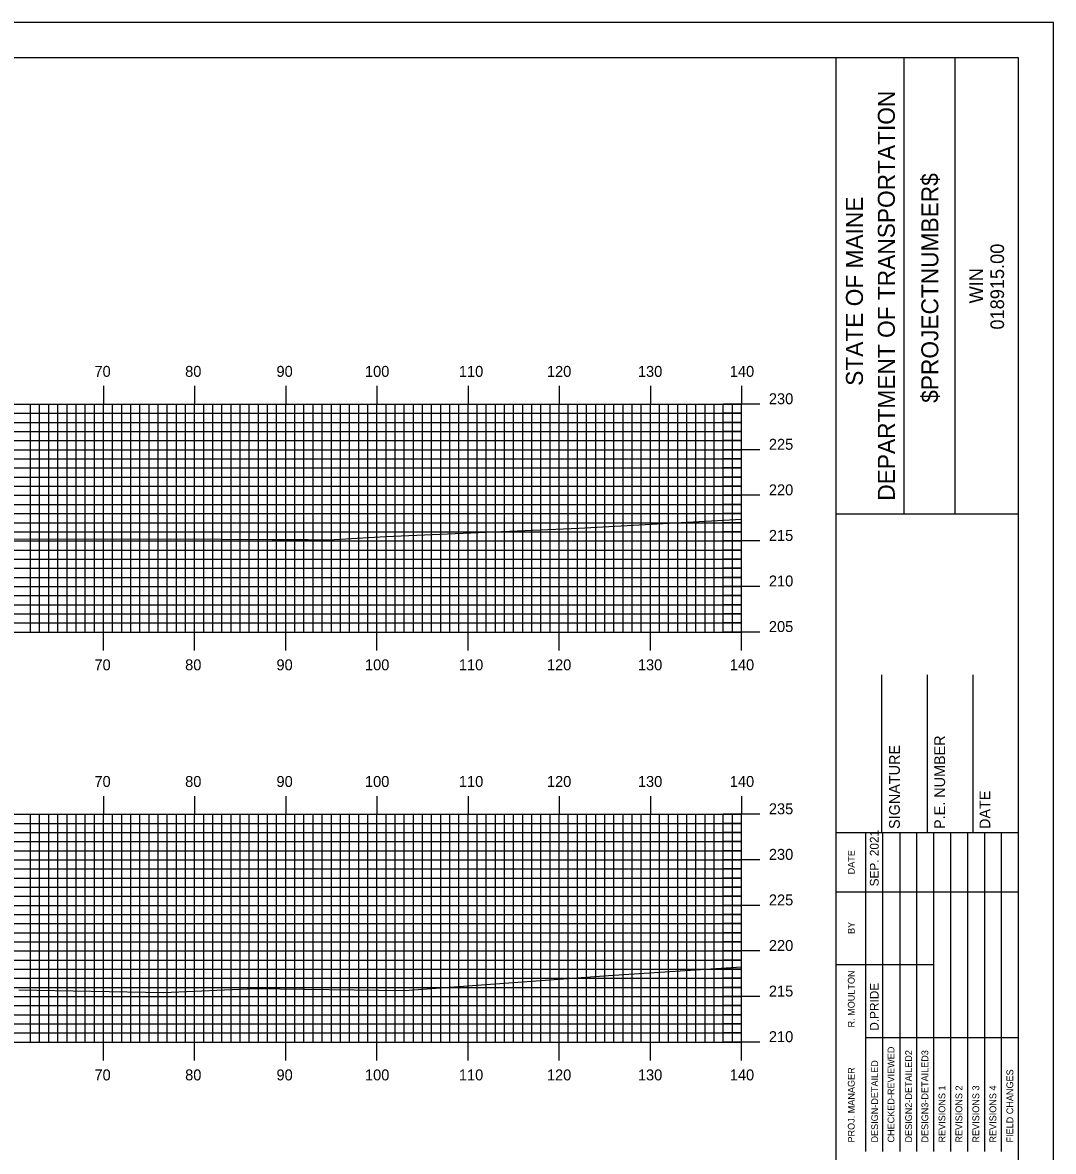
# Model space of a CAD drawing. Extents: x 1819244 to 1819587, y 442591 to 442811.
# Drawn here: x 1819470.8 to 1819583.9, y 442686.7 to 442810.5 of the extents above; entities that cross this region are included whole.
import ezdxf

# ---------------------------------------------------------------- set-up
doc = ezdxf.new("R2010")
doc.units = 0
for name, color, linetype in [('BORDER', 7, 'Continuous'), ('H_V ANNOTATION', 7, 'Continuous'), ('MAJOR', 7, 'Continuous'), ('MINOR', 7, 'Continuous'), ('PLOT BOUNDARY', 7, 'Continuous'), ('S_Roadway_Centerline', 7, 'Continuous')]:
    doc.layers.add(name, color=color, linetype=linetype)

msp = doc.modelspace()

# ---------------------------------------------------------------- linework, layer by layer
at = {"layer": 'BORDER'}
for p, q in [((1819560.06, 442596.67), (1819560.06, 442806.67)), ((1819567.52, 442756.66), (1819567.52, 442806.66)), ((1819573.11, 442756.66), (1819573.11, 442806.66)), ((1819560.07, 442756.65), (1819580.06, 442756.65)), ((1819565.06, 442721.67), (1819565.06, 442738.97)), ((1819570.06, 442721.67), (1819570.06, 442738.97)), ((1819575.06, 442721.67), (1819575.06, 442738.97)), ((1819560.06, 442721.67), (1819580.06, 442721.67))]:
    msp.add_line(p, q, dxfattribs=at)
msp.add_lwpolyline([(1819260.06, 442596.67), (1819580.06, 442596.67), (1819580.06, 442806.67), (1819260.06, 442806.67)], close=True, dxfattribs=at)
for points in [[(1819563.29, 442715.17), (1819563.29, 442721.67)], [(1819565.16, 442686.68), (1819565.16, 442721.67)], [(1819567.02, 442721.67), (1819567.02, 442686.68)], [(1819568.89, 442686.68), (1819568.89, 442721.67)], [(1819570.75, 442686.68), (1819570.75, 442721.67)], [(1819572.61, 442686.68), (1819572.61, 442721.67)], [(1819574.48, 442686.68), (1819574.48, 442721.67)], [(1819576.34, 442686.68), (1819576.34, 442721.67)], [(1819578.2, 442686.68), (1819578.2, 442721.67)], [(1819563.3, 442686.68), (1819563.3, 442720.26)], [(1819560.06, 442715.17), (1819580.06, 442715.17)], [(1819560.06, 442707.17), (1819563.3, 442707.17)], [(1819563.29, 442707.17), (1819570.75, 442707.17)], [(1819563.29, 442699.17), (1819580.06, 442699.17)]]:
    msp.add_lwpolyline(points, dxfattribs=at)
at = {"layer": 'MAJOR'}
for p, q in [((1819479.66, 442770.67), (1819479.66, 442768.67)), ((1819489.66, 442770.67), (1819489.66, 442768.67)), ((1819499.66, 442770.67), (1819499.66, 442768.67)), ((1819509.66, 442770.67), (1819509.66, 442768.67)), ((1819519.66, 442770.67), (1819519.66, 442768.67)), ((1819529.66, 442770.67), (1819529.66, 442768.67)), ((1819539.66, 442770.67), (1819539.66, 442768.67)), ((1819549.66, 442770.67), (1819549.66, 442768.67)), ((1819269.66, 442768.67), (1819549.66, 442768.67)), ((1819269.66, 442768.67), (1819549.66, 442768.67)), ((1819479.66, 442743.67), (1819479.66, 442768.67)), ((1819489.66, 442743.67), (1819489.66, 442768.67)), ((1819499.66, 442743.67), (1819499.66, 442768.67)), ((1819509.66, 442743.67), (1819509.66, 442768.67)), ((1819519.66, 442743.67), (1819519.66, 442768.67)), ((1819529.66, 442743.67), (1819529.66, 442768.67)), ((1819539.66, 442743.67), (1819539.66, 442768.67)), ((1819551.67, 442768.67), (1819547.66, 442768.67)), ((1819549.66, 442743.67), (1819549.66, 442768.67)), ((1819549.66, 442743.67), (1819549.66, 442768.67)), ((1819269.66, 442763.67), (1819549.66, 442763.67)), ((1819551.67, 442763.67), (1819547.66, 442763.67)), ((1819269.66, 442758.67), (1819549.66, 442758.67)), ((1819551.67, 442758.67), (1819547.66, 442758.67)), ((1819269.66, 442753.67), (1819549.66, 442753.67)), ((1819551.67, 442753.67), (1819547.66, 442753.67)), ((1819269.66, 442748.67), (1819549.66, 442748.67)), ((1819551.67, 442748.67), (1819547.66, 442748.67)), ((1819269.66, 442743.67), (1819549.66, 442743.67)), ((1819269.66, 442743.67), (1819549.66, 442743.67)), ((1819479.66, 442741.66), (1819479.66, 442743.67)), ((1819489.66, 442741.66), (1819489.66, 442743.67)), ((1819499.66, 442741.66), (1819499.66, 442743.67)), ((1819509.66, 442741.66), (1819509.66, 442743.67)), ((1819519.66, 442741.66), (1819519.66, 442743.67)), ((1819529.66, 442741.66), (1819529.66, 442743.67)), ((1819539.66, 442741.66), (1819539.66, 442743.67)), ((1819551.67, 442743.67), (1819547.66, 442743.67)), ((1819549.66, 442741.66), (1819549.66, 442743.67)), ((1819479.66, 442725.67), (1819479.66, 442723.67)), ((1819489.66, 442725.67), (1819489.66, 442723.67)), ((1819499.66, 442725.67), (1819499.66, 442723.67)), ((1819509.66, 442725.67), (1819509.66, 442723.67)), ((1819519.66, 442725.67), (1819519.66, 442723.67)), ((1819529.66, 442725.67), (1819529.66, 442723.67)), ((1819539.66, 442725.67), (1819539.66, 442723.67)), ((1819549.66, 442725.67), (1819549.66, 442723.67)), ((1819269.66, 442723.67), (1819549.66, 442723.67)), ((1819269.66, 442723.67), (1819549.66, 442723.67)), ((1819479.66, 442698.67), (1819479.66, 442723.67)), ((1819489.66, 442698.67), (1819489.66, 442723.67)), ((1819499.66, 442698.67), (1819499.66, 442723.67)), ((1819509.66, 442698.67), (1819509.66, 442723.67)), ((1819519.66, 442698.67), (1819519.66, 442723.67)), ((1819529.66, 442698.67), (1819529.66, 442723.67)), ((1819539.66, 442698.67), (1819539.66, 442723.67)), ((1819551.67, 442723.67), (1819547.66, 442723.67)), ((1819549.66, 442698.67), (1819549.66, 442723.67)), ((1819549.66, 442698.67), (1819549.66, 442723.67)), ((1819269.66, 442718.67), (1819549.66, 442718.67)), ((1819551.67, 442718.67), (1819547.66, 442718.67)), ((1819269.66, 442713.67), (1819549.66, 442713.67)), ((1819551.67, 442713.67), (1819547.66, 442713.67)), ((1819269.66, 442708.67), (1819549.66, 442708.67)), ((1819551.67, 442708.67), (1819547.66, 442708.67)), ((1819269.66, 442703.67), (1819549.66, 442703.67)), ((1819551.67, 442703.67), (1819547.66, 442703.67)), ((1819269.66, 442698.67), (1819549.66, 442698.67)), ((1819269.66, 442698.67), (1819549.66, 442698.67)), ((1819479.66, 442696.66), (1819479.66, 442698.67)), ((1819489.66, 442696.66), (1819489.66, 442698.67)), ((1819499.66, 442696.66), (1819499.66, 442698.67)), ((1819509.66, 442696.66), (1819509.66, 442698.67)), ((1819519.66, 442696.66), (1819519.66, 442698.67)), ((1819529.66, 442696.66), (1819529.66, 442698.67)), ((1819539.66, 442696.66), (1819539.66, 442698.67)), ((1819551.67, 442698.67), (1819547.66, 442698.67)), ((1819549.66, 442696.66), (1819549.66, 442698.67))]:
    msp.add_line(p, q, dxfattribs=at)
at = {"layer": 'MINOR'}
for p, q in [((1819471.66, 442743.67), (1819471.66, 442768.67)), ((1819472.66, 442743.67), (1819472.66, 442768.67)), ((1819473.66, 442743.67), (1819473.66, 442768.67)), ((1819474.66, 442743.67), (1819474.66, 442768.67)), ((1819475.66, 442743.67), (1819475.66, 442768.67)), ((1819476.66, 442743.67), (1819476.66, 442768.67)), ((1819477.66, 442743.67), (1819477.66, 442768.67)), ((1819478.66, 442743.67), (1819478.66, 442768.67)), ((1819480.66, 442743.67), (1819480.66, 442768.67)), ((1819481.66, 442743.67), (1819481.66, 442768.67)), ((1819482.66, 442743.67), (1819482.66, 442768.67)), ((1819483.66, 442743.67), (1819483.66, 442768.67)), ((1819484.66, 442743.67), (1819484.66, 442768.67)), ((1819485.66, 442743.67), (1819485.66, 442768.67)), ((1819486.66, 442743.67), (1819486.66, 442768.67)), ((1819487.66, 442743.67), (1819487.66, 442768.67)), ((1819488.66, 442743.67), (1819488.66, 442768.67)), ((1819490.66, 442743.67), (1819490.66, 442768.67)), ((1819491.66, 442743.67), (1819491.66, 442768.67)), ((1819492.66, 442743.67), (1819492.66, 442768.67)), ((1819493.66, 442743.67), (1819493.66, 442768.67)), ((1819494.66, 442743.67), (1819494.66, 442768.67)), ((1819495.66, 442743.67), (1819495.66, 442768.67)), ((1819496.66, 442743.67), (1819496.66, 442768.67)), ((1819497.66, 442743.67), (1819497.66, 442768.67)), ((1819498.66, 442743.67), (1819498.66, 442768.67)), ((1819500.66, 442743.67), (1819500.66, 442768.67)), ((1819501.66, 442743.67), (1819501.66, 442768.67)), ((1819502.66, 442743.67), (1819502.66, 442768.67)), ((1819503.66, 442743.67), (1819503.66, 442768.67)), ((1819504.66, 442743.67), (1819504.66, 442768.67)), ((1819505.66, 442743.67), (1819505.66, 442768.67)), ((1819506.66, 442743.67), (1819506.66, 442768.67)), ((1819507.66, 442743.67), (1819507.66, 442768.67)), ((1819508.66, 442743.67), (1819508.66, 442768.67)), ((1819510.66, 442743.67), (1819510.66, 442768.67)), ((1819511.66, 442743.67), (1819511.66, 442768.67)), ((1819512.66, 442743.67), (1819512.66, 442768.67)), ((1819513.66, 442743.67), (1819513.66, 442768.67)), ((1819514.66, 442743.67), (1819514.66, 442768.67)), ((1819515.66, 442743.67), (1819515.66, 442768.67)), ((1819516.66, 442743.67), (1819516.66, 442768.67)), ((1819517.66, 442743.67), (1819517.66, 442768.67)), ((1819518.66, 442743.67), (1819518.66, 442768.67)), ((1819520.66, 442743.67), (1819520.66, 442768.67)), ((1819521.66, 442743.67), (1819521.66, 442768.67)), ((1819522.66, 442743.67), (1819522.66, 442768.67)), ((1819523.66, 442743.67), (1819523.66, 442768.67)), ((1819524.66, 442743.67), (1819524.66, 442768.67)), ((1819525.66, 442743.67), (1819525.66, 442768.67)), ((1819526.66, 442743.67), (1819526.66, 442768.67)), ((1819527.66, 442743.67), (1819527.66, 442768.67)), ((1819528.66, 442743.67), (1819528.66, 442768.67)), ((1819530.66, 442743.67), (1819530.66, 442768.67)), ((1819531.66, 442743.67), (1819531.66, 442768.67)), ((1819532.66, 442743.67), (1819532.66, 442768.67)), ((1819533.66, 442743.67), (1819533.66, 442768.67)), ((1819534.66, 442743.67), (1819534.66, 442768.67)), ((1819535.66, 442743.67), (1819535.66, 442768.67)), ((1819536.66, 442743.67), (1819536.66, 442768.67)), ((1819537.66, 442743.67), (1819537.66, 442768.67)), ((1819538.66, 442743.67), (1819538.66, 442768.67)), ((1819540.66, 442743.67), (1819540.66, 442768.67)), ((1819541.66, 442743.67), (1819541.66, 442768.67)), ((1819542.66, 442743.67), (1819542.66, 442768.67)), ((1819543.66, 442743.67), (1819543.66, 442768.67)), ((1819544.66, 442743.67), (1819544.66, 442768.67)), ((1819545.66, 442743.67), (1819545.66, 442768.67)), ((1819546.66, 442743.67), (1819546.66, 442768.67)), ((1819547.66, 442743.67), (1819547.66, 442768.67)), ((1819548.66, 442743.67), (1819548.66, 442768.67)), ((1819269.66, 442767.67), (1819549.66, 442767.67)), ((1819549.66, 442767.67), (1819547.66, 442767.67)), ((1819269.66, 442766.67), (1819549.66, 442766.67)), ((1819549.66, 442766.67), (1819547.66, 442766.67)), ((1819269.66, 442765.67), (1819549.66, 442765.67)), ((1819549.66, 442765.67), (1819547.66, 442765.67)), ((1819269.66, 442764.67), (1819549.66, 442764.67)), ((1819549.66, 442764.67), (1819547.66, 442764.67)), ((1819269.66, 442762.67), (1819549.66, 442762.67)), ((1819549.66, 442762.67), (1819547.66, 442762.67)), ((1819269.66, 442761.67), (1819549.66, 442761.67)), ((1819549.66, 442761.67), (1819547.66, 442761.67)), ((1819269.66, 442760.67), (1819549.66, 442760.67)), ((1819549.66, 442760.67), (1819547.66, 442760.67)), ((1819269.66, 442759.67), (1819549.66, 442759.67)), ((1819549.66, 442759.67), (1819547.66, 442759.67)), ((1819269.66, 442757.67), (1819549.66, 442757.67)), ((1819549.66, 442757.67), (1819547.66, 442757.67)), ((1819269.66, 442756.67), (1819549.66, 442756.67)), ((1819549.66, 442756.67), (1819547.66, 442756.67)), ((1819269.66, 442755.67), (1819549.66, 442755.67)), ((1819549.66, 442755.67), (1819547.66, 442755.67)), ((1819269.66, 442754.67), (1819549.66, 442754.67)), ((1819549.66, 442754.67), (1819547.66, 442754.67)), ((1819269.66, 442752.67), (1819549.66, 442752.67)), ((1819549.66, 442752.67), (1819547.66, 442752.67)), ((1819269.66, 442751.67), (1819549.66, 442751.67)), ((1819549.66, 442751.67), (1819547.66, 442751.67)), ((1819269.66, 442750.67), (1819549.66, 442750.67)), ((1819549.66, 442750.67), (1819547.66, 442750.67)), ((1819269.66, 442749.67), (1819549.66, 442749.67)), ((1819549.66, 442749.67), (1819547.66, 442749.67)), ((1819269.66, 442747.67), (1819549.66, 442747.67)), ((1819549.66, 442747.67), (1819547.66, 442747.67)), ((1819269.66, 442746.67), (1819549.66, 442746.67)), ((1819549.66, 442746.67), (1819547.66, 442746.67)), ((1819269.66, 442745.67), (1819549.66, 442745.67)), ((1819549.66, 442745.67), (1819547.66, 442745.67)), ((1819269.66, 442744.67), (1819549.66, 442744.67)), ((1819549.66, 442744.67), (1819547.66, 442744.67)), ((1819471.66, 442698.67), (1819471.66, 442723.67)), ((1819472.66, 442698.67), (1819472.66, 442723.67)), ((1819473.66, 442698.67), (1819473.66, 442723.67)), ((1819474.66, 442698.67), (1819474.66, 442723.67)), ((1819475.66, 442698.67), (1819475.66, 442723.67)), ((1819476.66, 442698.67), (1819476.66, 442723.67)), ((1819477.66, 442698.67), (1819477.66, 442723.67)), ((1819478.66, 442698.67), (1819478.66, 442723.67)), ((1819480.66, 442698.67), (1819480.66, 442723.67)), ((1819481.66, 442698.67), (1819481.66, 442723.67)), ((1819482.66, 442698.67), (1819482.66, 442723.67)), ((1819483.66, 442698.67), (1819483.66, 442723.67)), ((1819484.66, 442698.67), (1819484.66, 442723.67)), ((1819485.66, 442698.67), (1819485.66, 442723.67)), ((1819486.66, 442698.67), (1819486.66, 442723.67)), ((1819487.66, 442698.67), (1819487.66, 442723.67)), ((1819488.66, 442698.67), (1819488.66, 442723.67)), ((1819490.66, 442698.67), (1819490.66, 442723.67)), ((1819491.66, 442698.67), (1819491.66, 442723.67)), ((1819492.66, 442698.67), (1819492.66, 442723.67)), ((1819493.66, 442698.67), (1819493.66, 442723.67)), ((1819494.66, 442698.67), (1819494.66, 442723.67)), ((1819495.66, 442698.67), (1819495.66, 442723.67)), ((1819496.66, 442698.67), (1819496.66, 442723.67)), ((1819497.66, 442698.67), (1819497.66, 442723.67)), ((1819498.66, 442698.67), (1819498.66, 442723.67)), ((1819500.66, 442698.67), (1819500.66, 442723.67)), ((1819501.66, 442698.67), (1819501.66, 442723.67)), ((1819502.66, 442698.67), (1819502.66, 442723.67)), ((1819503.66, 442698.67), (1819503.66, 442723.67)), ((1819504.66, 442698.67), (1819504.66, 442723.67)), ((1819505.66, 442698.67), (1819505.66, 442723.67)), ((1819506.66, 442698.67), (1819506.66, 442723.67)), ((1819507.66, 442698.67), (1819507.66, 442723.67)), ((1819508.66, 442698.67), (1819508.66, 442723.67)), ((1819510.66, 442698.67), (1819510.66, 442723.67)), ((1819511.66, 442698.67), (1819511.66, 442723.67)), ((1819512.66, 442698.67), (1819512.66, 442723.67)), ((1819513.66, 442698.67), (1819513.66, 442723.67)), ((1819514.66, 442698.67), (1819514.66, 442723.67)), ((1819515.66, 442698.67), (1819515.66, 442723.67)), ((1819516.66, 442698.67), (1819516.66, 442723.67)), ((1819517.66, 442698.67), (1819517.66, 442723.67)), ((1819518.66, 442698.67), (1819518.66, 442723.67)), ((1819520.66, 442698.67), (1819520.66, 442723.67)), ((1819521.66, 442698.67), (1819521.66, 442723.67)), ((1819522.66, 442698.67), (1819522.66, 442723.67)), ((1819523.66, 442698.67), (1819523.66, 442723.67)), ((1819524.66, 442698.67), (1819524.66, 442723.67)), ((1819525.66, 442698.67), (1819525.66, 442723.67)), ((1819526.66, 442698.67), (1819526.66, 442723.67)), ((1819527.66, 442698.67), (1819527.66, 442723.67)), ((1819528.66, 442698.67), (1819528.66, 442723.67)), ((1819530.66, 442698.67), (1819530.66, 442723.67)), ((1819531.66, 442698.67), (1819531.66, 442723.67)), ((1819532.66, 442698.67), (1819532.66, 442723.67)), ((1819533.66, 442698.67), (1819533.66, 442723.67)), ((1819534.66, 442698.67), (1819534.66, 442723.67)), ((1819535.66, 442698.67), (1819535.66, 442723.67)), ((1819536.66, 442698.67), (1819536.66, 442723.67)), ((1819537.66, 442698.67), (1819537.66, 442723.67)), ((1819538.66, 442698.67), (1819538.66, 442723.67)), ((1819540.66, 442698.67), (1819540.66, 442723.67)), ((1819541.66, 442698.67), (1819541.66, 442723.67)), ((1819542.66, 442698.67), (1819542.66, 442723.67)), ((1819543.66, 442698.67), (1819543.66, 442723.67)), ((1819544.66, 442698.67), (1819544.66, 442723.67)), ((1819545.66, 442698.67), (1819545.66, 442723.67)), ((1819546.66, 442698.67), (1819546.66, 442723.67)), ((1819547.66, 442698.67), (1819547.66, 442723.67)), ((1819548.66, 442698.67), (1819548.66, 442723.67)), ((1819269.66, 442722.67), (1819549.66, 442722.67)), ((1819269.66, 442721.67), (1819549.66, 442721.67)), ((1819549.66, 442722.67), (1819547.66, 442722.67)), ((1819549.66, 442721.67), (1819547.66, 442721.67)), ((1819269.66, 442720.67), (1819549.66, 442720.67)), ((1819549.66, 442720.67), (1819547.66, 442720.67)), ((1819269.66, 442719.67), (1819549.66, 442719.67)), ((1819549.66, 442719.67), (1819547.66, 442719.67)), ((1819269.66, 442717.67), (1819549.66, 442717.67)), ((1819269.66, 442716.67), (1819549.66, 442716.67)), ((1819549.66, 442717.67), (1819547.66, 442717.67)), ((1819549.66, 442716.67), (1819547.66, 442716.67)), ((1819269.66, 442715.67), (1819549.66, 442715.67)), ((1819549.66, 442715.67), (1819547.66, 442715.67)), ((1819269.66, 442714.67), (1819549.66, 442714.67)), ((1819549.66, 442714.67), (1819547.66, 442714.67)), ((1819269.66, 442712.67), (1819549.66, 442712.67)), ((1819269.66, 442711.67), (1819549.66, 442711.67)), ((1819549.66, 442712.67), (1819547.66, 442712.67)), ((1819549.66, 442711.67), (1819547.66, 442711.67)), ((1819269.66, 442710.67), (1819549.66, 442710.67)), ((1819549.66, 442710.67), (1819547.66, 442710.67)), ((1819269.66, 442709.67), (1819549.66, 442709.67)), ((1819549.66, 442709.67), (1819547.66, 442709.67)), ((1819269.66, 442707.67), (1819549.66, 442707.67)), ((1819269.66, 442706.67), (1819549.66, 442706.67)), ((1819549.66, 442707.67), (1819547.66, 442707.67)), ((1819549.66, 442706.67), (1819547.66, 442706.67)), ((1819269.66, 442705.67), (1819549.66, 442705.67)), ((1819549.66, 442705.67), (1819547.66, 442705.67)), ((1819269.66, 442704.67), (1819549.66, 442704.67)), ((1819549.66, 442704.67), (1819547.66, 442704.67)), ((1819269.66, 442702.67), (1819549.66, 442702.67)), ((1819269.66, 442701.67), (1819549.66, 442701.67)), ((1819549.66, 442702.67), (1819547.66, 442702.67)), ((1819549.66, 442701.67), (1819547.66, 442701.67)), ((1819269.66, 442700.67), (1819549.66, 442700.67)), ((1819549.66, 442700.67), (1819547.66, 442700.67)), ((1819269.66, 442699.67), (1819549.66, 442699.67)), ((1819549.66, 442699.67), (1819547.66, 442699.67))]:
    msp.add_line(p, q, dxfattribs=at)
at = {"layer": 'PLOT BOUNDARY'}
msp.add_lwpolyline([(1819243.88, 442590.55), (1819583.88, 442590.55), (1819583.88, 442810.55), (1819243.88, 442810.55)], close=True, dxfattribs=at)
at = {"layer": 'S_Roadway_Centerline'}
for points in [[(1819468.07, 442753.86), (1819486.97, 442753.9), (1819498.16, 442753.84), (1819502.13, 442753.82), (1819504.35, 442753.8), (1819510.65, 442754.16), (1819531.83, 442755.07), (1819549.66, 442756.05)], [(1819470.36, 442704.39), (1819486.24, 442704.12), (1819496.31, 442704.54), (1819512.57, 442704.32), (1819512.61, 442704.32), (1819512.62, 442704.32), (1819512.68, 442704.33), (1819535.05, 442705.99), (1819549.66, 442706.93)]]:
    msp.add_lwpolyline(points, dxfattribs=at)

# ---------------------------------------------------------------- texts
at = {"layer": 'BORDER'}
for s, height, p in [('DEPARTMENT OF TRANSPORTATION', 1.8635, (1819566.48, 442758.08)), ('$PROJECTNUMBER$', 1.8635, (1819571.25, 442768.82)), ('STATE OF MAINE', 1.8635, (1819562.98, 442770.69)), ('018915.00', 1.491, (1819578.46, 442776.86)), ('WIN', 1.491, (1819576.14, 442779.73)), ('P.E. NUMBER', 1.1811, (1819571.99, 442722.06)), ('SIGNATURE', 1.181, (1819567.03, 442722.06)), ('DATE', 1.181, (1819576.95, 442722.06)), ('SEP. 2021', 0.969, (1819564.71, 442715.76)), ('DATE', 0.743, (1819562.07, 442717.08)), ('BY', 0.743, (1819562.07, 442710.54)), ('R. MOULTON', 0.745, (1819562.07, 442700.28)), ('D.PRIDE', 0.969, (1819564.71, 442699.92)), ('CHECKED-REVIEWED', 0.7455, (1819566.43, 442687.65)), ('DESIGN2-DETAILED2', 0.7455, (1819568.36, 442687.65)), ('DESIGN3-DETAILED3', 0.7455, (1819570.15, 442687.65)), ('PROJ. MANAGER', 0.7455, (1819562.07, 442687.65)), ('DESIGN-DETAILED', 0.7455, (1819564.64, 442687.65)), ('FIELD CHANGES', 0.7455, (1819579.47, 442687.65)), ('REVISIONS 1', 0.7455, (1819572.02, 442687.65)), ('REVISIONS 2', 0.7455, (1819573.88, 442687.65)), ('REVISIONS 3', 0.7455, (1819575.74, 442687.65)), ('REVISIONS 4', 0.7455, (1819577.61, 442687.65))]:
    msp.add_text(s, height=height, rotation=90, dxfattribs=at).set_placement(p)
at = {"layer": 'H_V ANNOTATION'}
for s, p in [('70', (1819478.67, 442771.67)), ('80', (1819488.62, 442771.67)), ('90', (1819498.64, 442771.67)), ('100', (1819508.35, 442771.67)), ('110', (1819518.65, 442771.67)), ('120', (1819528.31, 442771.67)), ('130', (1819538.29, 442771.67)), ('140', (1819548.37, 442771.67)), ('230', (1819552.66, 442768.67)), ('225', (1819552.66, 442763.67)), ('220', (1819552.66, 442758.67)), ('215', (1819552.66, 442753.67)), ('210', (1819552.66, 442748.67)), ('205', (1819552.66, 442743.67)), ('70', (1819478.67, 442739.47)), ('80', (1819488.62, 442739.47)), ('90', (1819498.64, 442739.47)), ('100', (1819508.35, 442739.47)), ('110', (1819518.65, 442739.47)), ('120', (1819528.31, 442739.47)), ('130', (1819538.29, 442739.47)), ('140', (1819548.37, 442739.47)), ('70', (1819478.67, 442726.67)), ('80', (1819488.62, 442726.67)), ('90', (1819498.64, 442726.67)), ('100', (1819508.35, 442726.67)), ('110', (1819518.65, 442726.67)), ('120', (1819528.31, 442726.67)), ('130', (1819538.29, 442726.67)), ('140', (1819548.37, 442726.67)), ('235', (1819552.66, 442723.67)), ('230', (1819552.66, 442718.67)), ('225', (1819552.66, 442713.67)), ('220', (1819552.66, 442708.67)), ('215', (1819552.66, 442703.67)), ('210', (1819552.66, 442698.67)), ('70', (1819478.67, 442694.47)), ('80', (1819488.62, 442694.47)), ('90', (1819498.64, 442694.47)), ('100', (1819508.35, 442694.47)), ('110', (1819518.65, 442694.47)), ('120', (1819528.31, 442694.47)), ('130', (1819538.29, 442694.47)), ('140', (1819548.37, 442694.47))]:
    msp.add_text(s, height=1.2, dxfattribs=at).set_placement(p)

doc.saveas('drawing.dxf')
